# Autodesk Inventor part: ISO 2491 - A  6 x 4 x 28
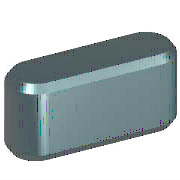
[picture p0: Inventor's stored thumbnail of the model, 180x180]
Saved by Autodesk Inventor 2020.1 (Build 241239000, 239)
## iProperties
Created: 2019-01
Part Number: ISO 2491 - A  6 x 4 x 28
Material: Stahl, weich
Description: Passfedern
Document SubType Name: Modeling
Standard: ISO 2491
Designer: lutzd
Standard Revision: First edition 1974-08-15
Standards Organization: ISO
Language: de-DE
Size Designation: A  6 x 4 x 28
Categories: <MemberInstance><Categories><Category DisplayName="Wellenteile" InternalName="7f7aeb1f-a693-4053-b835-cee3144e0d98" Mnemonic="SHFT"><Category DisplayName="Passf
Mass: 4.95473 g
Surface Area: 5.42077 cm^2
Volume: 0.631175 cm^3
Density: 7.85 g/cm^3
Appearance: Halbpoliert
IsCustomPart: 0
Author: lutzd
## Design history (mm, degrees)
workplane "Work Plane1"
workplane "Work Plane2"
sketch "Skizze1"
  geometry: L1 (3, 3)-(25, 3); L2 (25, -3)-(3, -3); L3 (0, 9.4)-(0, -7.4) reference; L4 (-5, 0)-(30, 0) reference; L5 (28, 0)-(28, 7); A1 r 3 centre (3, 0) between (3, 3) and (3, -3); A2 r 3 centre (25, 0) between (25, -3) and (25, 3)
  constraints: 6 end point, 5 point on circle, 4 tangent, 3 point on line, 2 centre point, 1 horizontal, 1 parallel, 1 perpendicular
  dimensions: "d0" = 3 radius of A1 (= 0.5 x PB); "d13" = 3 radius of A2 (= 0.5 x PB); "d14" = 28 distance between parallel lines of L5 L3 (= NLG)
extrude "Körper1" new body sketch "Skizze1" taper "d3" = 0 deg; stored distance "d4" = 10
workplane "Work Plane3"
body "Solid1"
chamfer "Fase1" distance "d8" = 0.4 (= PHH); stored, may be unused: second distance "d9" = 0.4 (= PHH), angle "d15" = 45 deg
other parameters: "d1" = -2.5 (= -PNT), "d2" = 1.5 (= PH - PNT), "NLG" = 28 [user parameter; used in 1 equation term], "PB" = 6 [user parameter; used in 2 equation terms], "PNT" = 2.5 [user parameter; used in 2 equation terms], "PH" = 4 [user parameter; used in 1 equation term], "PHH" = 0.4 [user parameter; used in 2 equation terms], "d10" = 0, "d16" = 0, "d17" = 0, "d18" = 0, "RR" = 0.16 [user parameter], "WDMIN" = 17 [user parameter], "WDMAX" = 22 [user parameter], "PLB1" = 28 [user parameter], "PLB2" = 28 [user parameter], "PUEB" = 1.8 [user parameter]
